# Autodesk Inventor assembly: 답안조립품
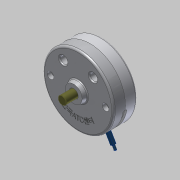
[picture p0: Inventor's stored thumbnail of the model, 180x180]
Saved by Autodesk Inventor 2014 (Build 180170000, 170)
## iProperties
Created: 2015-06
Part Number: 답안조립품
Document SubType Name: Assembly
Designer: MYHOME
Author: MYHOME
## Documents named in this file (10)
- C:\Documents and Settings\MYHOME\바탕 화면\450631V1045\답안조립품.iam
- C:\Documents and Settings\MYHOME\바탕 화면\450631V1045\본체.ipt
- C:\Documents and Settings\MYHOME\바탕 화면\450631V1045\덮개.ipt
- C:\Documents and Settings\MYHOME\바탕 화면\450631V1045\베어링62_22.ipt
- C:\Documents and Settings\MYHOME\바탕 화면\450631V1045\M10x35.ipt
- C:\Documents and Settings\MYHOME\바탕 화면\450631V1045\축.ipt
- C:\Documents and Settings\MYHOME\바탕 화면\450631V1045\멈춤링.ipt
- C:\Documents and Settings\MYHOME\바탕 화면\450631V1045\슬라이더2.ipt
- C:\Documents and Settings\MYHOME\바탕 화면\450631V1045\슬라이더.ipt
- C:\Documents and Settings\MYHOME\바탕 화면\450631V1045\평행핀.ipt
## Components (7 placed, 4 different names)
1. KS B 2023 62/22 - 22 x 50 x 14:1 — 각도:1
2. KS B 2023 62/22 - 22 x 50 x 14:2 — 각도:2
3. KS B 1336 22 x 1.2:1 — 각도:3
4. KS B 1336 22 x 1.2:2 — 각도:4
5. KS B 1320 B B 5 x  20:1 — 플러쉬:1
6. KS B 1003 - 미터 M 10 x 35:1
7. KS B 1003 - 미터 M 10 x 35:2
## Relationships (5: Angle 4, Flush 1)
- 플러쉬:1 [Flush]: KS B 1320 B B 5 x  20:1
- 각도:1 [Angle]: KS B 2023 62/22 - 22 x 50 x 14:1
- 각도:2 [Angle]: KS B 2023 62/22 - 22 x 50 x 14:2
- 각도:3 [Angle]: KS B 1336 22 x 1.2:1
- 각도:4 [Angle]: KS B 1336 22 x 1.2:2
